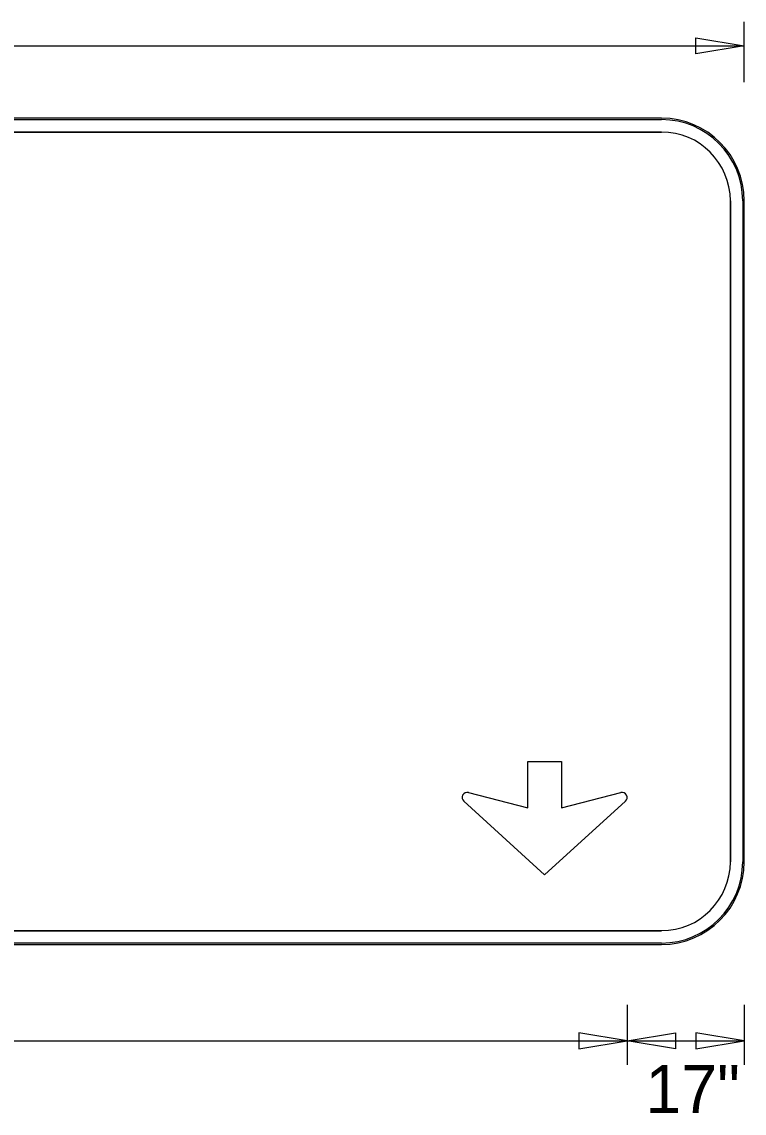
# Model space of a CAD drawing. Extents: x 2149934 to 2150188, y 145114 to 145238.
# Drawn here: x 2149957.85 to 2149966.6, y 145135.91 to 145149.12 of the extents above; entities that cross this region are included whole.
import ezdxf

# ---------------------------------------------------------------- set-up
doc = ezdxf.new("R2010")
doc.units = 0
for name, color, linetype in [('GSBWFILL', 7, 'Continuous'), ('GSCOLORFILL', 7, 'Continuous'), ('GSDIMS', 7, 'Continuous'), ('GSOUTLINE', 7, 'Continuous')]:
    doc.layers.add(name, color=color, linetype=linetype)

msp = doc.modelspace()

# ---------------------------------------------------------------- linework, layer by layer
at = {"layer": 'GSBWFILL'}
for p, q in [((2149965.596, 145147.954), (2149940.596, 145147.954)), ((2149940.596, 145147.787), (2149965.596, 145147.787)), ((2149966.43, 145146.954), (2149966.43, 145138.954)), ((2149966.596, 145138.954), (2149966.596, 145146.954)), ((2149965.596, 145138.12), (2149940.598, 145138.12)), ((2149940.598, 145137.954), (2149965.596, 145137.954))]:
    msp.add_line(p, q, dxfattribs=at)
for points in [[(2149963.257, 145139.792), (2149963.977, 145139.607), (2149963.977, 145140.168), (2149964.383, 145140.168), (2149964.383, 145139.607), (2149965.103, 145139.792)], [(2149965.16, 145139.687), (2149964.18, 145138.795), (2149963.201, 145139.687)]]:
    msp.add_lwpolyline(points, dxfattribs=at)
for centre, radius, start, end in [((2149965.596, 145146.954), 1, 0, 90), ((2149965.596, 145146.954), 0.833, 0, 90), ((2149963.242, 145139.732), 0.0615, 75.5925, 227.6952), ((2149965.118, 145139.732), 0.0615, 312.3048, 104.4075), ((2149965.596, 145138.954), 1, 270, 0), ((2149965.596, 145138.954), 0.833, 270, 0)]:
    msp.add_arc(centre, radius, start, end, dxfattribs=at)
at = {"layer": 'GSCOLORFILL'}
for p, q in [((2149965.596, 145147.954), (2149940.596, 145147.954)), ((2149965.596, 145147.954), (2149940.596, 145147.954)), ((2149965.596, 145147.954), (2149940.596, 145147.954)), ((2149940.596, 145147.937), (2149965.596, 145147.937)), ((2149940.596, 145147.787), (2149965.596, 145147.787)), ((2149966.43, 145146.954), (2149966.43, 145138.954)), ((2149966.58, 145146.954), (2149966.58, 145138.954)), ((2149966.596, 145138.954), (2149966.596, 145146.954)), ((2149966.596, 145138.954), (2149966.596, 145146.954)), ((2149966.596, 145138.954), (2149966.596, 145146.954)), ((2149965.596, 145138.12), (2149940.598, 145138.12)), ((2149965.596, 145137.97), (2149940.596, 145137.97)), ((2149940.596, 145137.954), (2149965.596, 145137.954)), ((2149940.596, 145137.954), (2149965.596, 145137.954)), ((2149940.598, 145137.954), (2149965.596, 145137.954))]:
    msp.add_line(p, q, dxfattribs=at)
for points in [[(2149963.257, 145139.792), (2149963.977, 145139.607), (2149963.977, 145140.168), (2149964.383, 145140.168), (2149964.383, 145139.607), (2149965.103, 145139.792)], [(2149965.16, 145139.687), (2149964.18, 145138.795), (2149963.201, 145139.687)]]:
    msp.add_lwpolyline(points, dxfattribs=at)
for centre, radius, start, end in [((2149965.596, 145146.954), 1, 0, 90), ((2149965.596, 145146.954), 1, 0, 90), ((2149965.596, 145146.954), 1, 0, 90), ((2149965.596, 145146.954), 0.983, 0, 90), ((2149965.596, 145146.954), 0.833, 0, 90), ((2149963.242, 145139.732), 0.0615, 75.5925, 227.6952), ((2149965.118, 145139.732), 0.0615, 312.3048, 104.4075), ((2149965.596, 145138.954), 1, 270, 0), ((2149965.596, 145138.954), 1, 270, 0), ((2149965.596, 145138.954), 0.833, 270, 0), ((2149965.596, 145138.954), 1, 270, 0), ((2149965.596, 145138.954), 0.983, 270, 0)]:
    msp.add_arc(centre, radius, start, end, dxfattribs=at)
at = {"layer": 'GSDIMS'}
for p, q in [((2149966.596, 145148.391), (2149966.596, 145149.12)), ((2149939.596, 145148.829), (2149966.596, 145148.829)), ((2149966.596, 145148.391), (2149966.596, 145148.391)), ((2149965.18, 145137.224), (2149965.18, 145136.495)), ((2149965.18, 145137.224), (2149965.18, 145136.495)), ((2149966.596, 145137.224), (2149966.596, 145136.495)), ((2149966.596, 145137.224), (2149966.596, 145136.495)), ((2149941.013, 145136.787), (2149965.18, 145136.787)), ((2149965.18, 145136.787), (2149966.596, 145136.787))]:
    msp.add_line(p, q, dxfattribs=at)
for points in [[(2149966.596, 145148.829), (2149966.013, 145148.732), (2149966.013, 145148.926)], [(2149965.18, 145136.787), (2149964.596, 145136.884), (2149964.596, 145136.69)], [(2149965.18, 145136.787), (2149965.763, 145136.884), (2149965.763, 145136.69)], [(2149966.596, 145136.787), (2149966.013, 145136.884), (2149966.013, 145136.69)]]:
    msp.add_lwpolyline(points, close=True, dxfattribs=at)
at = {"layer": 'GSOUTLINE'}
for p, q in [((2149965.596, 145147.954), (2149940.596, 145147.954)), ((2149965.596, 145147.787), (2149940.596, 145147.787)), ((2149966.43, 145138.954), (2149966.43, 145146.954)), ((2149966.596, 145138.954), (2149966.596, 145146.954)), ((2149940.596, 145138.12), (2149965.596, 145138.12)), ((2149940.596, 145137.954), (2149965.596, 145137.954))]:
    msp.add_line(p, q, dxfattribs=at)
for points in [[(2149963.257, 145139.792), (2149963.977, 145139.607), (2149963.977, 145140.168), (2149964.383, 145140.168), (2149964.383, 145139.607), (2149965.103, 145139.792)], [(2149965.16, 145139.687), (2149964.18, 145138.795), (2149963.201, 145139.687)]]:
    msp.add_lwpolyline(points, dxfattribs=at)
for centre, radius, start, end in [((2149965.596, 145146.954), 1, 0, 90), ((2149965.596, 145146.954), 0.833, 0, 90), ((2149963.242, 145139.732), 0.0615, 75.5925, 227.6952), ((2149965.118, 145139.732), 0.0615, 312.3048, 104.4075), ((2149965.596, 145138.954), 1, 270, 0), ((2149965.596, 145138.954), 0.833, 270, 0)]:
    msp.add_arc(centre, radius, start, end, dxfattribs=at)

# ---------------------------------------------------------------- texts
at = {"layer": 'GSDIMS'}
msp.add_text('17"', height=0.5833, dxfattribs=at).set_placement((2149965.401, 145135.912))

doc.saveas('drawing.dxf')
